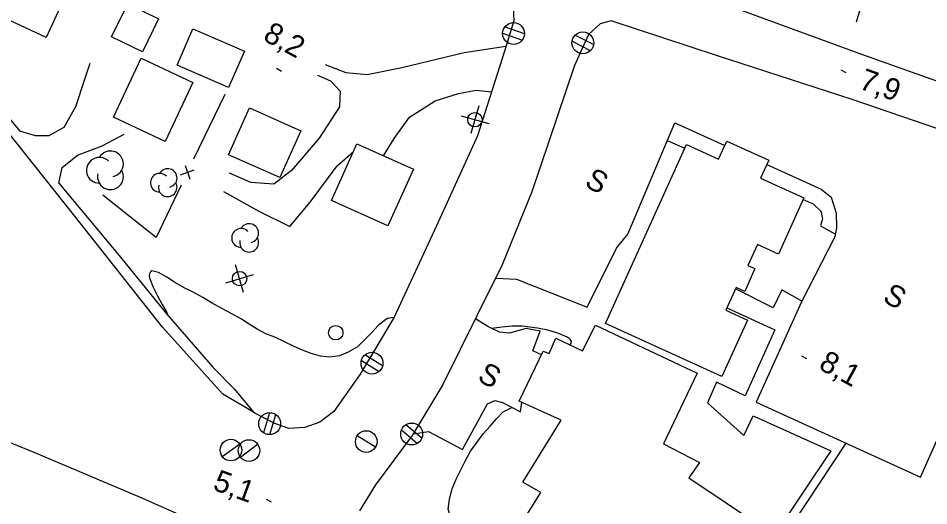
# Model space of a CAD drawing. Extents: x 219136 to 222520, y 5421589 to 5424530.
# Drawn here: x 221256.8 to 221383.2, y 5422936.2 to 5423003.9 of the extents above; entities that cross this region are included whole.
import ezdxf

# ---------------------------------------------------------------- set-up
doc = ezdxf.new("R2010")
doc.units = 0
for name, color, linetype in [('Level 19', 7, 'Continuous'), ('Level 2', 7, 'Continuous'), ('Level 21', 7, 'Continuous'), ('Level 22', 7, 'Continuous'), ('Level 3', 7, 'Continuous'), ('Level 31', 7, 'Continuous'), ('Level 36', 7, 'Continuous'), ('Level 37', 7, 'Continuous'), ('Level 44', 7, 'Continuous'), ('Level 52', 7, 'Continuous')]:
    doc.layers.add(name, color=color, linetype=linetype)

msp = doc.modelspace()

# ---------------------------------------------------------------- linework, layer by layer
at = {"layer": 'Level 19'}
for points in [[(221324.49, 5422999.99), (221324.48, 5422999.99), (221318.69, 5422999.11), (221310.03, 5422997.01), (221305.21, 5422996.02), (221302.29, 5422996.3), (221299.41, 5422997.41)], [(221256.95, 5422988.24), (221259.09, 5422987.61), (221261.04, 5422987.62), (221263.13, 5422988.79), (221264.77, 5422991.62), (221266.03, 5422995.57), (221266.72, 5422997.66)], [(221298.29, 5422995.97), (221300.13, 5422995.2), (221301.46, 5422993.78), (221301.36, 5422991.61), (221298.55, 5422987.24), (221294.7, 5422982.76), (221292.26, 5422980.83), (221289.07, 5422981.08), (221286.1, 5422982.36)], [(221307.48, 5422984.8), (221308.97, 5422987.2), (221311.06, 5422990.15), (221314.63, 5422992.43), (221317.9, 5422993.44), (221320.36, 5422993.91), (221322.47, 5422993.67)], [(221262.4, 5422980.97), (221262.87, 5422983.16), (221265, 5422984.87), (221268.41, 5422986.16), (221271.46, 5422987.8)], [(221285.26, 5422979.83), (221290.16, 5422977.11), (221294.45, 5422974.98), (221297.28, 5422978.34), (221301.05, 5422983.39), (221303.31, 5422985.4)]]:
    msp.add_lwpolyline(points, dxfattribs=at)
at = {"layer": 'Level 2'}
for points in [[(221286.39, 5422962.86), (221285.01, 5422963.57), (221283.7, 5422964.33), (221282.37, 5422965.11), (221281.05, 5422965.86), (221279.81, 5422966.46), (221278.59, 5422967.16), (221277.37, 5422967.96), (221276.22, 5422968.57), (221275.31, 5422968.82), (221275.11, 5422968.66), (221275, 5422968.41), (221274.95, 5422968.15), (221274.98, 5422967.85), (221275.47, 5422966.54), (221276.11, 5422965.35), (221276.76, 5422964.16), (221277.38, 5422963.02), (221277.44, 5422962.77)], [(221308.92, 5422962.33), (221308.04, 5422962.22), (221307.78, 5422962.08), (221306.72, 5422961.21), (221305.81, 5422960.23), (221304.84, 5422959.22), (221303.87, 5422958.25), (221302.55, 5422957.53), (221301.35, 5422957.03), (221300.04, 5422956.85), (221298.71, 5422956.96), (221297.44, 5422957.32), (221296.22, 5422957.8), (221295.06, 5422958.3), (221293.72, 5422958.94), (221292.37, 5422959.6), (221291.14, 5422960.09), (221289.95, 5422960.73), (221288.84, 5422961.39), (221287.74, 5422962.1), (221286.39, 5422962.86)], [(221333.4, 5422958.52), (221333.54, 5422958.77), (221333.56, 5422959.02), (221333.41, 5422959.26), (221333.21, 5422959.46), (221332.98, 5422959.6), (221331.66, 5422960.14), (221330.29, 5422960.56), (221328.84, 5422960.85), (221326.73, 5422961.13), (221325.27, 5422961.12), (221323.94, 5422961.01), (221322.49, 5422960.82)], [(221316.65, 5422935.13), (221316.52, 5422935.43), (221316.45, 5422935.73), (221316.62, 5422937.12), (221317.02, 5422938.56), (221317.54, 5422939.91), (221318.2, 5422941.19), (221318.8, 5422942.4), (221319.53, 5422943.77), (221320.46, 5422945.01), (221321.33, 5422946.2), (221322.28, 5422947.25), (221323.13, 5422948.21), (221324.1, 5422949.22), (221325.3, 5422949.85)]]:
    msp.add_lwpolyline(points, dxfattribs=at)
at = {"layer": 'Level 21'}
for points in [[(221377.94, 5423146.6), (221366.37, 5423111.05), (221353.65, 5423073.3), (221339.12, 5423028.71), (221335.37, 5423016.91), (221335.75, 5423014.84), (221336.46, 5423013.52), (221337.43, 5423012.59), (221340.21, 5423011.28), (221373.85, 5422998.89), (221397.41, 5422990.55)], [(221240.97, 5423054.43), (221281.87, 5423032.45), (221309.38, 5423017.21), (221320.67, 5423011.12), (221323.15, 5423009.45), (221324.76, 5423007.51), (221325.49, 5423005.58), (221325.56, 5423003.53), (221324.33, 5422999.48), (221320.51, 5422987.57), (221314.85, 5422975.06), (221308.95, 5422962.38), (221304.21, 5422954.45), (221300.57, 5422949.28), (221298.65, 5422947.78), (221296.53, 5422947.04), (221294.31, 5422946.91), (221292.39, 5422947.63), (221289.61, 5422949.05), (221289.4, 5422949.17), (221285.15, 5422951.71), (221276.79, 5422960.98), (221264.62, 5422976.42), (221246.86, 5422998.7)], [(221241.25, 5423008.65), (221247.89, 5422999.49), (221254.12, 5422991.7), (221256.95, 5422988.24)], [(221476.62, 5422949.49), (221470.24, 5422952.48), (221444.38, 5422964.74), (221430, 5422971.51), (221420.95, 5422975.49), (221411.75, 5422979.37), (221394.87, 5422984.97), (221372.55, 5422992.6), (221353.72, 5422998.72), (221339.08, 5423003.54), (221337.56, 5423003.12), (221335.92, 5423001.63), (221333.97, 5422997.31), (221328.07, 5422979.8), (221323.97, 5422969.65), (221320.45, 5422962.57), (221315.68, 5422952.95), (221311.47, 5422945.93), (221306.35, 5422939.09), (221304.13, 5422935.5)], [(221262.4, 5422980.97), (221270.52, 5422971.23), (221277.39, 5422962.82), (221283.78, 5422955.42), (221286.78, 5422952.4), (221289.4, 5422949.17)], [(221197.19, 5422971.44), (221214.72, 5422962.94), (221238.02, 5422952.15), (221258.9, 5422943.63), (221273.7, 5422937.39), (221282.56, 5422933.43), (221287.39, 5422930.65), (221290.07, 5422929.29)]]:
    msp.add_lwpolyline(points, dxfattribs=at)
at = {"layer": 'Level 22'}
for points in [[(221346.87, 5422986.91), (221349.31, 5422985.85)], [(221365.74, 5422978.71), (221367.14, 5422978.1), (221368.2, 5422977.09), (221368.43, 5422976.05), (221368.16, 5422975.06), (221370.23, 5422973.93)], [(221365.57, 5422964.61), (221362.77, 5422966.16), (221361.59, 5422963.67), (221356.36, 5422966.34)], [(221355.15, 5422963.68), (221361.81, 5422960.61), (221357.7, 5422951.48), (221353.7, 5422953.36), (221352.48, 5422950.5), (221357.52, 5422945.94), (221358.78, 5422948.69), (221369.57, 5422943.8), (221357.78, 5422926.18), (221347.72, 5422911.07), (221342.06, 5422903.08)], [(221343.23, 5422902.24), (221351.73, 5422914.96), (221362.51, 5422930.95), (221371.7, 5422944.87)]]:
    msp.add_lwpolyline(points, dxfattribs=at)
at = {"layer": 'Level 3'}
for p, q in [((221292.62, 5422996.94), (221293.32, 5422996.55)), ((221370.97, 5422996.74), (221371.68, 5422996.35)), ((221365.49, 5422957.01), (221366.2, 5422956.63)), ((221291.19, 5422937.13), (221291.89, 5422936.74))]:
    msp.add_line(p, q, dxfattribs=at)
at = {"layer": 'Level 31'}
for points in [[(221255.78, 5423013.14), (221264.31, 5423009.17), (221260.62, 5423001.23), (221252.09, 5423005.2)], [(221274.01, 5422999.23), (221269.72, 5423001.33), (221271.95, 5423005.89), (221276.24, 5423003.8)], [(221281.01, 5423002.42), (221288.15, 5422999.33), (221285.97, 5422994.29), (221278.83, 5422997.38)], [(221273.8, 5422998.33), (221280.99, 5422994.97), (221277.17, 5422986.8), (221269.98, 5422990.16)], [(221293.07, 5422981.77), (221285.97, 5422984.94), (221288.87, 5422991.43), (221295.97, 5422988.26)], [(221338.28, 5422961.5), (221349.53, 5422986.34), (221354, 5422984.31), (221355.14, 5422986.83), (221360.96, 5422984.19), (221359.83, 5422981.69), (221365.85, 5422978.96), (221362.31, 5422971.15), (221359.4, 5422972.47), (221358.08, 5422969.56), (221359.05, 5422969.12), (221357.62, 5422965.97), (221356.43, 5422966.5), (221355, 5422963.35), (221358.02, 5422961.98), (221354.47, 5422954.16)], [(221303.79, 5422986.47), (221311.63, 5422982.94), (221308.09, 5422975.07), (221300.25, 5422978.59)], [(221360.24, 5422933.13), (221353.2, 5422922.26), (221350.95, 5422923.93), (221348.55, 5422920.67), (221338.7, 5422926.69), (221338.23, 5422925.26), (221335.26, 5422926.46), (221335.77, 5422928.46), (221327.12, 5422934.55), (221329.32, 5422938.02), (221326.82, 5422939.47), (221332.15, 5422948.09), (221326.32, 5422950.71), (221329.65, 5422957.64), (221330.46, 5422957.36), (221331.4, 5422959.45), (221335.09, 5422957.73), (221336.92, 5422961.27), (221351.02, 5422954.62), (221346.36, 5422944.8), (221351.35, 5422942.22), (221349.88, 5422940.06)]]:
    msp.add_lwpolyline(points, close=True, dxfattribs=at)
at = {"layer": 'Level 36'}
for p, q in [((221374.22, 5423007.18), (221373.12, 5423003.35)), ((221327.03, 5423001.74), (221324.29, 5423002.69)), ((221324.01, 5423001.82), (221326.75, 5423000.87)), ((221333.66, 5423000.69), (221336.25, 5422999.39)), ((221336.64, 5423000.23), (221334.05, 5423001.53)), ((221320.71, 5422991.72), (221319.61, 5422987.89)), ((221318.25, 5422990.36), (221322.08, 5422989.26)), ((221288.05, 5422965.82), (221286.92, 5422969.65)), ((221285.57, 5422967.17), (221289.4, 5422968.3)), ((221304.41, 5422956.36), (221306.88, 5422954.84)), ((221307.35, 5422955.64), (221304.88, 5422957.16)), ((221291.65, 5422949.12), (221290.82, 5422946.34)), ((221291.71, 5422946.1), (221292.54, 5422948.88)), ((221309.98, 5422946.72), (221312.21, 5422944.86)), ((221312.78, 5422945.58), (221310.55, 5422947.44)), ((221306.36, 5422944.31), (221303.82, 5422945.91)), ((221285.06, 5422943.05), (221287.5, 5422944.79)), ((221287.6, 5422942.94), (221289.98, 5422944.76))]:
    msp.add_line(p, q, dxfattribs=at)
for centre, radius in [((221325.53, 5423001.77), 1.52), ((221335.15, 5423000.47), 1.52), ((221320.16, 5422989.8), 1), ((221287.49, 5422967.74), 1), ((221300.84, 5422960.22), 1), ((221305.88, 5422955.99), 1.52), ((221291.67, 5422947.6), 1.52), ((221311.38, 5422946.16), 1.52), ((221305.08, 5422945.11), 1.5), ((221286.29, 5422943.93), 1.5), ((221288.8, 5422943.86), 1.5)]:
    msp.add_circle(centre, radius, dxfattribs=at)
at = {"layer": 'Level 37'}
for p, q in [((221279.91, 5422983.45), (221280.57, 5422981.56)), ((221279.3, 5422982.17), (221281.19, 5422982.84))]:
    msp.add_line(p, q, dxfattribs=at)
for points in [[(221285.44, 5422993.32), (221281.11, 5422984.31)], [(221279.38, 5422980.7), (221275.89, 5422973.45), (221274.36, 5422974.67)], [(221274.36, 5422974.67), (221268.52, 5422979.34)]]:
    msp.add_lwpolyline(points, dxfattribs=at)
at = {"layer": 'Level 44'}
for centre, radius, start, end in [((221269.56, 5422983.67), 1.79, 282.2692, 149.7262), ((221268.02, 5422982.78), 1.79, 44.1153, 269.8039), ((221277.51, 5422981.71), 1.29, 282.2692, 149.7262), ((221269.56, 5422981.88), 1.79, 166.9368, 29.6212), ((221276.4, 5422981.06), 1.29, 44.1153, 269.8039), ((221277.51, 5422980.42), 1.29, 166.9368, 29.6212), ((221288.82, 5422974.05), 1.31, 282.2692, 149.7262), ((221287.7, 5422973.39), 1.31, 44.1153, 269.8039), ((221288.82, 5422972.74), 1.31, 166.9368, 29.6212)]:
    msp.add_arc(centre, radius, start, end, dxfattribs=at)
at = {"layer": 'Level 52'}
for points in [[(221323.05, 5422967.79), (221325.95, 5422967.68), (221335.77, 5422963.75), (221339.81, 5422971.97), (221341.39, 5422973.92), (221347.9, 5422989.35), (221354.86, 5422986.2)], [(221360.68, 5422983.57), (221368.25, 5422980.15), (221369.62, 5422979.06), (221370.33, 5422976.81), (221370.38, 5422974.81), (221370.16, 5422973.54), (221365.51, 5422964.5), (221359.22, 5422950.57), (221382.02, 5422940.15), (221390.86, 5422960.03), (221389.1, 5422960.89), (221388.67, 5422961.72), (221389, 5422962.97), (221398.22, 5422983.86)], [(221329.42, 5422957.16), (221328.2, 5422957.7), (221329.22, 5422960.42), (221327.3, 5422960.8), (221324.98, 5422960.17), (221323.57, 5422960.32), (221321.94, 5422961.07), (221320.25, 5422962.17)], [(221311.62, 5422946.18), (221313.73, 5422946.5), (221318.44, 5422944.01), (221321.93, 5422950.37), (221322.92, 5422950.81), (221323.98, 5422950.54), (221326.49, 5422949.23), (221326.69, 5422950.55)]]:
    msp.add_lwpolyline(points, dxfattribs=at)

# ---------------------------------------------------------------- texts
at = {"layer": 'Level 3'}
for s, rotation, p in [('8,2', 331.383, (221290.59, 5423000.92)), ('7,9', 340.3517, (221373.35, 5422994.17)), ('8,1', 331.383, (221367.74, 5422955.28)), ('5,1', 339.9359, (221283.63, 5422938.47))]:
    msp.add_text(s, height=3, rotation=rotation, dxfattribs=at).set_placement(p)
at = {"layer": 'Level 52'}
for p in [(221335.24, 5422980.65), (221376.63, 5422964.64), (221320.36, 5422953.65)]:
    msp.add_text('S', height=3, rotation=331.383, dxfattribs=at).set_placement(p)

doc.saveas('drawing.dxf')
